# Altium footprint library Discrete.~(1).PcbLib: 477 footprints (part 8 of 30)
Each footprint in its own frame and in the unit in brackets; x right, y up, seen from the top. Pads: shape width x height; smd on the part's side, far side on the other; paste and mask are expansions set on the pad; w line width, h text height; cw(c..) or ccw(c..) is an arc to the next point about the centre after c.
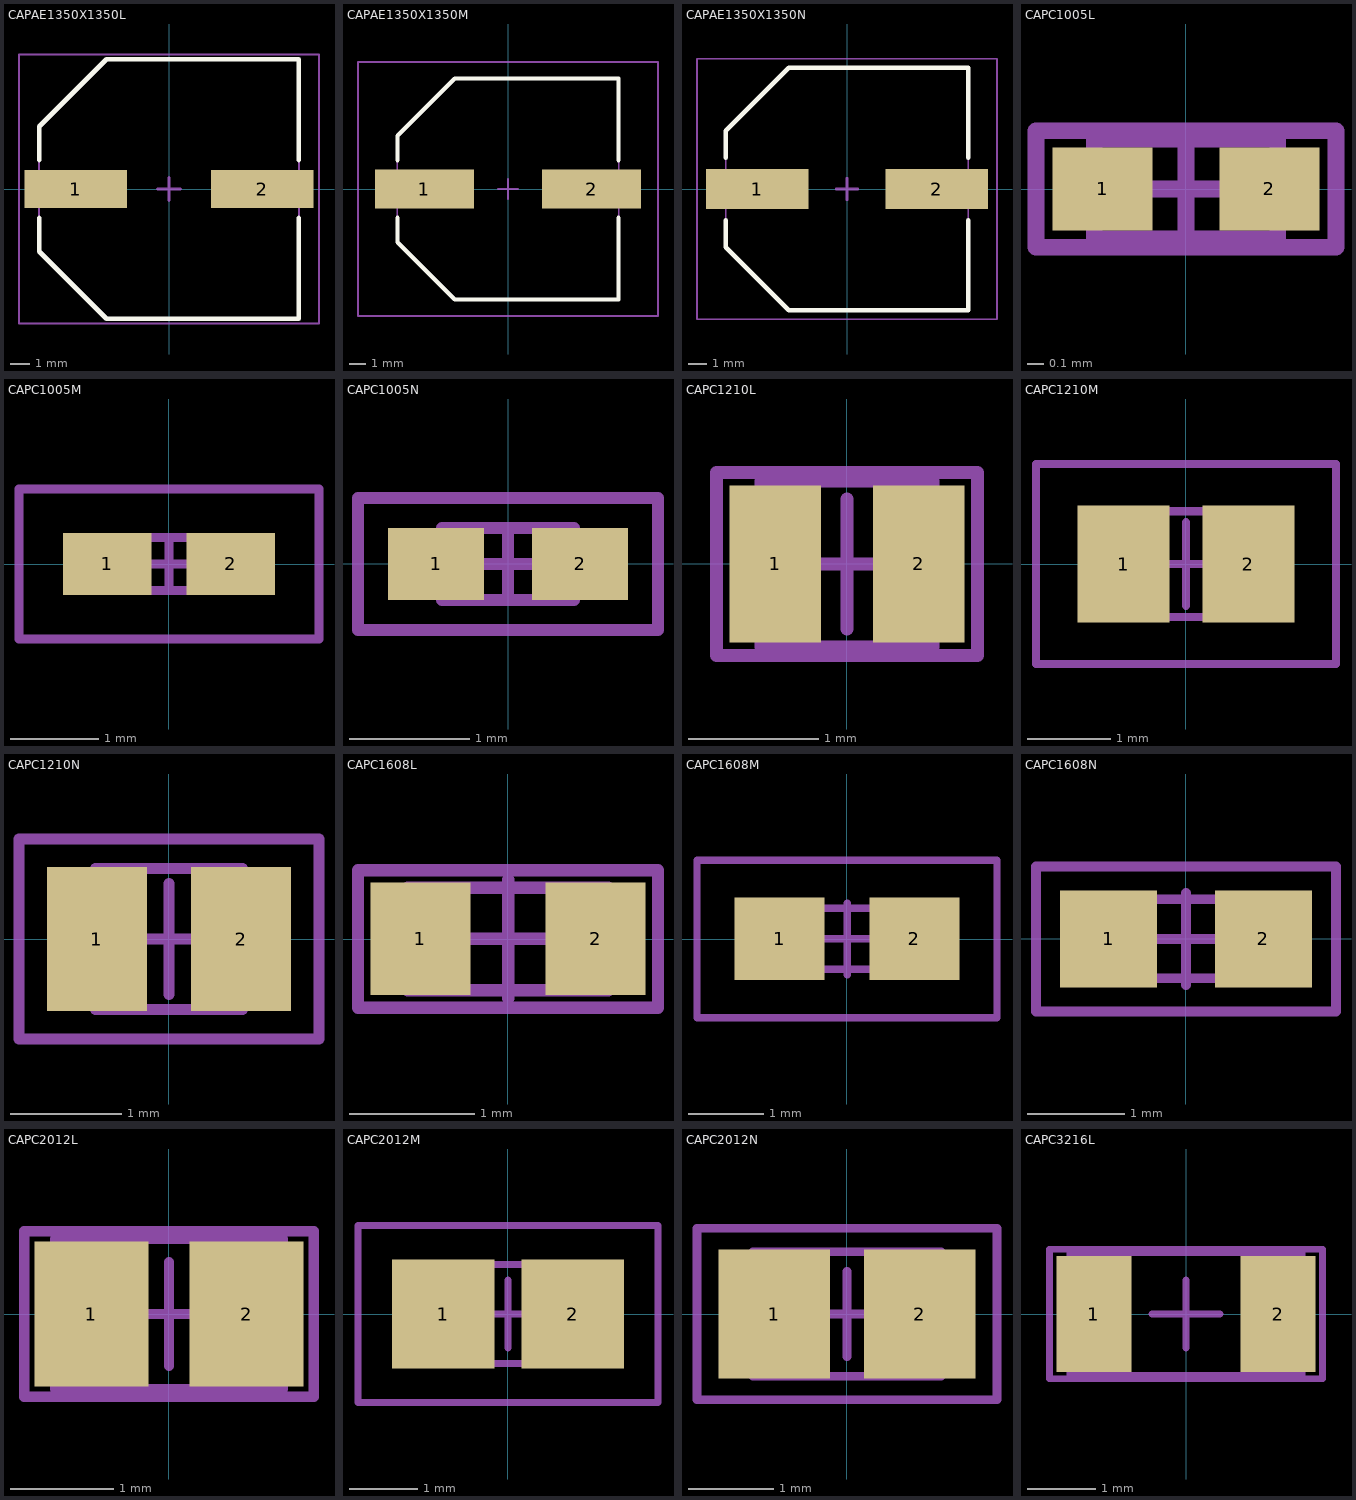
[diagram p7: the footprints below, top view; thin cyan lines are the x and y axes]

## CAPAE1350X1350L [mm]
height 6
pads (2):
  rect 5.35x2 smd: 1(-4.85,0) 2(4.85,0)
Top Overlay:
  lines w0.254: -6.75,-1.5 -6.75,-3.25 -3.25,-6.75 6.75,-6.75 6.75,-1.5 ; -6.75,1.5 -6.75,3.25 -3.25,6.75 6.75,6.75 6.75,1.5
Mechanical 13:
  lines w0.1: -6.75,-3.25 -6.75,3.25 -3.25,6.75 6.75,6.75 6.75,-6.75 -3.25,-6.75 -6.75,-3.25
Mechanical 15:
  lines w0.1: -7.8,-7 7.8,-7 7.8,7 -7.8,7 -7.8,-7
  lines w0.15: -0.6,0 0.6,0 ; 0,-0.6 0,0.6
3D body: height 16, standoff 3, extent -6.201,-6.238 6.25,6.238
3D body: height 3, standoff 0, extent -6.75,-6.75 6.75,6.75

## CAPAE1350X1350M [mm]
height 6
pads (2):
  rect 6.05x2.4 smd: 1(-5.1,0) 2(5.1,0)
Top Overlay:
  lines w0.254: -6.75,-1.75 -6.75,-3.25 -3.25,-6.75 6.75,-6.75 6.75,-1.75 ; -6.75,1.75 -6.75,3.25 -3.25,6.75 6.75,6.75 6.75,1.75
Mechanical 13:
  lines w0.1: -6.75,-3.25 -6.75,3.25 -3.25,6.75 6.75,6.75 6.75,-6.75 -3.25,-6.75 -6.75,-3.25
Mechanical 15:
  lines w0.1: -9.15,-7.75 -9.15,7.75 9.15,7.75 9.15,-7.75 -9.15,-7.75
  lines w0.15: -0.6,0 0.6,0 ; 0,-0.6 0,0.6
3D body: height 16, standoff 3, extent -6.201,-6.238 6.25,6.238
3D body: height 3, standoff 0, extent -6.75,-6.75 6.75,6.75

## CAPAE1350X1350N [mm]
height 6
pads (2):
  rect 5.7x2.2 smd: 1(-5,0) 2(5,0)
Top Overlay:
  lines w0.254: -6.75,-1.75 -6.75,-3.25 -3.25,-6.75 6.75,-6.75 6.75,-1.75 ; -6.75,1.75 -6.75,3.25 -3.25,6.75 6.75,6.75 6.75,1.75
Mechanical 13:
  lines w0.1: -6.75,-3.25 -3.25,-6.75 6.75,-6.75 6.75,6.75 -3.25,6.75 -6.75,3.25 -6.75,-3.25
Mechanical 15:
  lines w0.1: -8.35,-7.25 8.35,-7.25 8.35,7.25 -8.35,7.25 -8.35,-7.25
  lines w0.15: -0.6,0 0.6,0 ; 0,-0.6 0,0.6
3D body: height 3, standoff 0, extent -6.75,-6.75 6.75,6.75
3D body: height 16, standoff 3, extent -6.201,-6.238 6.25,6.238

## CAPC1005L [mm] "Chip Capacitor, Body 1.0x0.5mm, IPC High Density"
height 0.6
pads (2):
  rect 0.6x0.5 smd: 1(-0.5,0) 2(0.5,0)
Mechanical 13:
  lines w0.1: -0.55,-0.3 0.55,-0.3 0.55,0.3 -0.55,0.3 -0.55,-0.3
Mechanical 15:
  lines w0.1: -0.3,0 0.3,0 ; 0,-0.3 0,0.3 ; -0.9,-0.35 0.9,-0.35 0.9,0.35 -0.9,0.35 -0.9,-0.35
3D body "C 0402.STEP": height 0.51, standoff -0.01, extent -0.5,-0.26 0.5,0.26

## CAPC1005M [mm] "Chip Capacitor, Body 1.0x0.5mm, IPC Low Density"
height 0.6
pads (2):
  rect 1x0.7 smd: 1(-0.7,0) 2(0.7,0)
Mechanical 13:
  lines w0.1: -0.55,-0.3 0.55,-0.3 0.55,0.3 -0.55,0.3 -0.55,-0.3
Mechanical 15:
  lines w0.1: -0.3,0 0.3,0 ; 0,-0.3 0,0.3 ; -1.7,-0.85 1.7,-0.85 1.7,0.85 -1.7,0.85 -1.7,-0.85
3D body "C 0402.STEP": height 0.51, standoff -0.01, extent -0.5,-0.26 0.5,0.26

## CAPC1005N [mm] "Chip Capacitor, Body 1.0x0.5mm, IPC Medium Density"
height 0.6
pads (2):
  rect 0.8x0.6 smd: 1(-0.6,0) 2(0.6,0)
Mechanical 13:
  lines w0.1: -0.55,-0.3 -0.55,0.3 0.55,0.3 0.55,-0.3 -0.55,-0.3
Mechanical 15:
  lines w0.1: -0.3,0 0.3,0 ; 0,-0.3 0,0.3 ; -1.25,-0.55 -1.25,0.55 1.25,0.55 1.25,-0.55 -1.25,-0.55
3D body "C 0402.STEP": height 0.51, standoff -0.01, extent -0.5,-0.26 0.5,0.26

## CAPC1210L [mm] "Chip Capacitor, Body 1.2x1.0mm, IPC High Density"
height 1.02
pads (2):
  rect 0.7x1.2 smd: 1(-0.55,0) 2(0.55,0)
Mechanical 13:
  lines w0.1: -0.66,-0.635 0.66,-0.635 0.66,0.635 -0.66,0.635 -0.66,-0.635
Mechanical 15:
  lines w0.1: -0.5,0 0.5,0 ; 0,-0.5 0,0.5 ; -1,-0.7 1,-0.7 1,0.7 -1,0.7 -1,-0.7
3D body: height 1.02, standoff 0, extent -0.66,-0.635 0.66,0.635

## CAPC1210M [mm] "Chip Capacitor, Body 1.2x1.0mm, IPC Low Density"
height 1.02
pads (2):
  rect 1.1x1.4 smd: 1(-0.75,0) 2(0.75,0)
Mechanical 13:
  lines w0.1: -0.66,-0.635 0.66,-0.635 0.66,0.635 -0.66,0.635 -0.66,-0.635
Mechanical 15:
  lines w0.1: -0.5,0 0.5,0 ; 0,-0.5 0,0.5 ; -1.8,-1.2 1.8,-1.2 1.8,1.2 -1.8,1.2 -1.8,-1.2
3D body: height 1.02, standoff 0, extent -0.66,-0.635 0.66,0.635

## CAPC1210N [mm] "Chip Capacitor, Body 1.2x1.0mm, IPC Medium Density"
height 1.02
pads (2):
  rect 0.9x1.3 smd: 1(-0.65,0) 2(0.65,0)
Mechanical 13:
  lines w0.1: -0.66,-0.635 -0.66,0.635 0.66,0.635 0.66,-0.635 -0.66,-0.635
Mechanical 15:
  lines w0.1: -0.5,0 0.5,0 ; 0,-0.5 0,0.5 ; -1.35,-0.9 -1.35,0.9 1.35,0.9 1.35,-0.9 -1.35,-0.9
3D body: height 1.02, standoff 0, extent -0.66,-0.635 0.66,0.635

## CAPC1608L [mm] "Chip Capacitor, Body 1.6x0.8mm, IPC High Density"
height 0.85
pads (2):
  rect 0.8x0.9 smd: 1(-0.7,0) 2(0.7,0)
Mechanical 13:
  lines w0.1: -0.8,-0.41 -0.8,0.41 0.8,0.41 0.8,-0.41 -0.8,-0.41
Mechanical 15:
  lines w0.1: -0.475,0 0.475,0 ; 0,-0.475 0,0.475 ; -1.2,-0.55 -1.2,0.55 1.2,0.55 1.2,-0.55 -1.2,-0.55
3D body "C 0603.STEP": height 0.81, standoff -0.01, extent -0.8,-0.41 0.8,0.41

## CAPC1608M [mm] "Chip Capacitor, Body 1.6x0.8mm, IPC Low Density"
height 0.85
pads (2):
  rect 1.2x1.1 smd: 1(-0.9,0) 2(0.9,0)
Mechanical 13:
  lines w0.1: -0.8,-0.406 0.8,-0.406 0.8,0.41 -0.8,0.41 -0.8,-0.406
Mechanical 15:
  lines w0.1: -0.475,0 0.475,0 ; 0,-0.475 0,0.475 ; -2,-1.05 2,-1.05 2,1.05 -2,1.05 -2,-1.05
3D body "C 0603.STEP": height 0.81, standoff -0.01, extent -0.8,-0.41 0.8,0.41

## CAPC1608N [mm] "Chip Capacitor, Body 1.6x0.8mm, IPC Medium Density"
height 0.85
pads (2):
  rect 1x1 smd: 1(-0.8,0) 2(0.8,0)
Mechanical 13:
  lines w0.1: -0.8,-0.406 -0.8,0.41 0.813,0.41 0.813,-0.406 -0.8,-0.406
Mechanical 15:
  lines w0.1: -0.475,0 0.475,0 ; 0,-0.475 0,0.475 ; -1.55,-0.75 -1.55,0.75 1.55,0.75 1.55,-0.75 -1.55,-0.75
3D body "C 0603.STEP": height 0.81, standoff -0.01, extent -0.8,-0.41 0.8,0.41

## CAPC2012L [mm] "Chip Capacitor, Body 2.0x1.3mm, IPC High Density"
height 1.1
pads (2):
  rect 1.1x1.4 smd: 1(-0.75,0) 2(0.75,0)
Mechanical 13:
  lines w0.1: -1.1,-0.725 1.1,-0.725 1.1,0.725 -1.1,0.725 -1.1,-0.725
Mechanical 15:
  lines w0.1: -0.5,0 0.5,0 ; 0,-0.5 0,0.5 ; -1.4,-0.8 1.4,-0.8 1.4,0.8 -1.4,0.8 -1.4,-0.8
3D body "C 0805.STEP": height 0.51, standoff -0.01, extent -1,-0.61 1,0.61

## CAPC2012M [mm] "Chip Capacitor, Body 2.0x1.3mm, IPC Low Density"
height 1.1
pads (2):
  rect 1.5x1.6 smd: 1(-0.95,0) 2(0.95,0)
Mechanical 13:
  lines w0.1: -1.1,-0.725 -1.1,0.725 1.1,0.725 1.1,-0.725 -1.1,-0.725
Mechanical 15:
  lines w0.1: -0.5,0 0.5,0 ; 0,-0.5 0,0.5 ; -2.2,-1.3 -2.2,1.3 2.2,1.3 2.2,-1.3 -2.2,-1.3
3D body "C 0805.STEP": height 0.51, standoff -0.01, extent -1,-0.61 1,0.61

## CAPC2012N [mm] "Chip Capacitor, Body 2.0x1.3mm, IPC Medium Density"
height 1.1
pads (2):
  rect 1.3x1.5 smd: 1(-0.85,0) 2(0.85,0)
Mechanical 13:
  lines w0.1: -1.1,-0.725 -1.1,0.725 1.1,0.725 1.1,-0.725 -1.1,-0.725
Mechanical 15:
  lines w0.1: -0.5,0 0.5,0 ; 0,-0.5 0,0.5 ; -1.75,-1 -1.75,1 1.75,1 1.75,-1 -1.75,-1
3D body "C 0805.STEP": height 0.51, standoff -0.01, extent -1,-0.61 1,0.61

## CAPC3216L [mm] "Chip Capacitor, Body 3.2x1.6mm, IPC High Density"
height 1.35
pads (2):
  rect 1.1x1.7 smd: 1(-1.35,0) 2(1.35,0)
Mechanical 13:
  lines w0.1: -1.7,-0.9 -1.7,0.9 1.7,0.9 1.7,-0.9 -1.7,-0.9
Mechanical 15:
  lines w0.1: -0.5,0 0.5,0 ; 0,-0.5 0,0.5 ; -2,-0.95 -2,0.95 2,0.95 2,-0.95 -2,-0.95
3D body "C 1206.STEP": height 1.21, standoff -0.01, extent -1.6,-0.81 1.6,0.81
